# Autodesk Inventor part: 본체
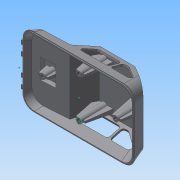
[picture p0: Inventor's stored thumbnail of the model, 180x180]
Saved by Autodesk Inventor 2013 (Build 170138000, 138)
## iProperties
Created: 2015-05
Part Number: 본체
Material: 일반
Document SubType Name: Modeling
Designer: ST3
Density: 1 g/cm^3
Author: ST3
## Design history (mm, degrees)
sketch "스케치1"
  geometry: L1 (-61, 0)-(61, 0); L2 (-61, 0)-(-58.588, 9); L3 (-58.588, 9)-(-19, 11.075); L4 (-19, 11.075)-(-6.549, 31); L5 (-6.549, 31)-(31, 31); L6 (31, 31)-(61, 11); L7 (57.412, 13.392)-(61, 0); L8 (61, 0)-(61, 11); 2 further points
  constraints: 16 end point, 2 horizontal, 2 midpoint, 1 coincident, 1 perpendicular, 1 point on line
  dimensions: "d0" = 122 distance of L1.start L1.end; "d2" = 105 deg angle of L1 L2; "d4" = 42 horizontal distance of L3.end L1.start; "d5" = 30 horizontal distance of L5.end L1.end; "d7" = 31 vertical distance of L1.end L5.end; "d8" = 125 deg angle of L4 L3; "d9" = 9 vertical distance of L2.end L1.start; "d10" = 3 deg angle of L1 L3; "d11" = 105 deg angle of L1 L7; "d99" = 20 vertical distance of L6.end L5.end
extrude "돌출1" new body sketch "스케치1" stored distance "d12" = 76; taper "d13" = 0 deg
sketch "스케치2"
  geometry: L1 (31, 38)-(11.075, 38) reference; L2 (31, -38)-(31, 38) reference; L3 (0, 38)-(31, 29.694); L4 (0, -38)-(31, -29.694); L5 (11.075, -38)-(31, -38) reference; L6 (0, -38)-(9, -38) reference; L7 (9, -38)-(11.075, -38) reference; L8 (11.075, 38)-(9, 38) reference; L9 (0, 38)-(31, 38); L10 (31, 38)-(31, 29.694); L11 (31, -29.694)-(31, -38); L12 (31, -38)-(0, -38); 1 further point
  constraints: 12 end point, 3 collinear, 2 point on line, 1 perpendicular
extrude "돌출2" cut sketch "스케치2" stored distance "d16" = 130; taper "d17" = 0 deg
sketch "스케치3"
  geometry: L1 (-58.588, 9)-(-61, 0) reference; L2 (-19, 11.075)-(-58.588, 9) reference; L3 (-50.479, 9.425)-(-50.741, 14.418); L4 (-50.741, 14.418)-(-30.741, 15.466); L5 (-30.741, 15.466)-(-30.479, 10.473); 1 further point
  constraints: 6 end point, 3 perpendicular, 2 point on line
  dimensions: "d18" = 20 horizontal distance of L3.end L4.end; "d20" = 11 distance from line of L3 L1.end; "d21" = 5 distance between parallel lines of L2 L4
extrude "돌출3" join sketch "스케치3" stored distance "d22" = 26; taper "d23" = 0 deg
feature "쉘1" dims "d24" = 2
sketch "스케치4"
  geometry: L1 (122, -76)-(122, 0) reference; L2 (0, 0)-(122, 0) reference; L3 (0, 0)-(0, -76) reference; L4 (122, -76)-(0, -76) reference; L5 (121, -1)-(121, -75); L6 (121, -75)-(1, -75); L7 (1, -75)-(1, -1); L8 (1, -1)-(121, -1); 1 further point
  constraints: 8 end point, 3 other
  dimensions: "d25" = 1 distance between parallel lines of L2 L8
extrude "돌출4" cut sketch "스케치4" distance "d26" = 1; taper "d27" = 0 deg
sketch "스케치6"
  geometry: L1 (121.732, -0.268)-(121.732, -75.732) reference; C1 r 3 at (100.732, -38); 1 further point
  constraints: 1 centre point, 1 horizontal alignment
  dimensions: "d33" = 6 diameter of C1; "d35" = 21 distance from line of L1 C1.centre
extrude "돌출5" join sketch "스케치6" stored distance "d36" = 10; taper "d37" = 2 deg
sketch "스케치8"
  geometry: L1 (34.732, 2)-(44.732, 2); L2 (58.929, 0)-(-58.929, 0) reference; L3 (34.732, 2)-(29.619, 31); L4 (44.732, 2)-(47.863, 19.758); L5 (42.732, 1)-(36.732, 1) reference; L6 (39.732, 1)-(39.732, 25.179); L7 (57.412, 13.392)-(31, 31) reference; L8 (31, 31)-(-6.549, 31) reference; 1 further point
  constraints: 8 end point, 3 point on line, 1 horizontal, 1 midpoint, 1 perpendicular
  dimensions: "d38" = 2 distance between parallel lines of L2 L1; "d39" = 20 deg angle of L4 L3; "d40" = 10 deg angle of L6 L3; "d41" = 5 distance from line of L6 L1.start; "d42" = 10 distance of L1.end L1.start
extrude "돌출6" join sketch "스케치8" stored distance "d43" = 2; taper "d44" = 0 deg
feature "면 기울기1" dims angle "d45" = 2.5 deg
feature "면 기울기2" dims angle "d46" = 2.5 deg
feature "면 기울기3" dims angle "d47" = 2.5 deg
feature "면 기울기4" dims angle "d48" = 2.5 deg
feature "면 기울기5" dims angle "d49" = 2.5 deg
feature "면 기울기6" dims angle "d50" = 2.5 deg
feature "면 기울기7" dims angle "d51" = 2.5 deg
feature "면 기울기8" dims angle "d52" = 2.5 deg
sketch "스케치9"
  geometry: L1 (-50.741, 14.418)-(-30.741, 15.466) reference; L2 (-50.741, 14.418)-(-30.741, 15.466); L3 (-30.945, 15.456)-(-26.502, 34.9); L4 (-26.502, 34.9)-(-51.656, 31.886); L5 (-51.656, 31.886)-(-50.741, 14.418); 1 further point
  constraints: 8 end point, 1 collinear, 1 perpendicular, 1 point on line
extrude "돌출7" cut sketch "스케치9" stored distance "d53" = 20; taper "d54" = 0 deg
sketch "스케치10"
  geometry: L1 (121.732, -0.268)-(121.732, -75.732) reference; C1 r 3 at (60.732, -60); 1 further point
  constraints: 1 centre point
  dimensions: "d55" = 61 distance from line of L1 C1.centre; "d56" = 22 vertical distance of C1.centre point (61, -38); "d57" = 6 diameter of C1
extrude "돌출8" join sketch "스케치10" stored distance "d58" = 20; taper "d59" = 2 deg
node "작업 평면1"
sketch "스케치11"
  geometry: L1 (3.268, 1)-(-2.732, 1) reference; L2 (4.246, 29)-(-3.71, 29) reference; L3 (3.268, 1)-(4.246, 29) reference; L4 (-30.394, 29)-(-55.675, 12.146) reference; L5 (-55.675, 12.146)-(-58.929, 0) reference; L6 (58.929, 0)-(-58.929, 0) reference; L7 (58.929, 0)-(57.033, 7.079) reference; L8 (57.033, 7.079)-(17.856, 9.132) reference; L9 (17.856, 9.132)-(5.441, 29) reference; L10 (5.441, 29)-(-30.394, 29) reference; L11 (-2.732, 1)-(-3.71, 29) reference; L12 (-4.732, 3)-(5.268, 3); L13 (5.268, 3)-(8.882, 23.494); L14 (-4.732, 3)-(-9.317, 29); L15 (0.268, 1)-(0.268, 29); 1 further point
  constraints: 8 end point, 2 midpoint, 2 point on line, 1 parallel, 1 perpendicular
  dimensions: "d61" = 20 deg angle of L13 L14; "d62" = 10 deg angle of L15 L14; "d63" = 2 distance between parallel lines of L12 L1; "d64" = 10 distance of L12.end L12.start; "d65" = 5 distance from line of L15 L12.start
extrude "돌출9" join sketch "스케치11" stored distance "d66" = 2; taper "d67" = 0 deg
feature "면 기울기9" dims angle "d68" = 2.5 deg
feature "면 기울기10" dims angle "d69" = 2.5 deg
feature "면 기울기11" dims angle "d70" = 2.5 deg
feature "면 기울기12" dims angle "d71" = 2.5 deg
sketch "스케치12"
  geometry: C1 r 3 at (0, 0) reference; 2 further points
  constraints: 1 coincident
sketch "스케치13"
  geometry: C1 r 3 at (0, 0) reference; 2 further points
  constraints: 1 coincident
hole "구멍1" sketch "스케치12" diameter "d72" = 3.242; stored, may be unused: countersink angle "d76" = 90 deg, drill point angle "d78" = 118 deg; dims "d73" = 9, "d74" = 4, "d75" = 2, "d77" = 11
sketch "스케치14"
  geometry: C1 r 3 at (0, 0) reference; 2 further points
  constraints: 1 coincident
hole "구멍2" sketch "스케치14" at (0, 0) diameter "d79" = 3.242; stored, may be unused: countersink angle "d83" = 90 deg, drill point angle "d85" = 118 deg; dims "d80" = 9, "d81" = 4, "d82" = 2, "d84" = 11
sketch "스케치16"
  geometry: L1 (67.281, -67.426)-(67.281, 8.038) reference; 2 further points
  constraints: 1 horizontal alignment, 1 other
  dimensions: "d90" = 50 distance from line of L1 point (17.281, -29.694)
feature "엠보싱1" sketch "스케치16" dims "d91" = 0.5, "d92" = 0
fillet "모깎기1" dims "d93" = 12
fillet "모깎기2" dims "d94" = 12
fillet "모깎기3" dims "d95" = 12
fillet "모깎기4" dims "d96" = 12
sketch "스케치18"
  geometry: L1 (37.549, 0)-(49.849, -8.489) reference; L2 (0, 0)-(37.549, 0) reference; L3 (-12.451, -20.628)-(0, 0) reference; L4 (57.725, -20)-(35.991, -5); L5 (35.991, -5)-(2.822, -5); L6 (2.822, -5)-(-6.231, -20); L7 (-42.592, -31.058)-(55.69, -31.058) reference; L8 (-6.231, -20)-(57.725, -20); L9 (27.769, -5)-(27.769, -20); L10 (29.725, -5)-(29.725, -20); 5 further points; 2 other entities
  constraints: 12 end point, 4 point on line, 2 parallel, 2 perpendicular, 2 other
  dimensions: "d100" = 5 distance between parallel lines of L2 L5; "d101" = 15 vertical distance of L6.end L5.end; "d102" = 15 vertical distance of L4.start L4.end; "d103" = 5 distance between parallel lines of L6 L3; "d104" = 5 distance between parallel lines of L1 L4; "d105" = 34 distance from line of L9 L6.end; "d106" = 28 distance from line of L4.start L10
extrude "돌출10" cut sketch "스케치18" stored distance "d107" = 2; taper "d108" = 0 deg
fillet "모깎기5" dims "d109" = 3
node "작업 평면3"
sketch "스케치19"
  geometry: 1 further point
node "작업 평면4"
sketch "스케치20"
  geometry: L1 (-26.141, 0)-(26.141, 0) reference; A1 r 2 centre (-21, 0) between (-19, 0) and (-23, 0); A2 r 2 centre (-10, 0) between (-8, 0) and (-12, 0); 1 further point
  constraints: 6 point on line, 4 point on circle, 2 centre point
  dimensions: "d112" = 4 diameter of A2; "d114" = 4 diameter of A1; "d115" = 11 distance of A2.centre A1.centre; "d116" = 10 horizontal distance of point (0, -4.177) A2.centre
extrude "돌출11" join sketch "스케치20" stored distance "d117" = 2; taper "d118" = 0 deg
node "솔리드1"
mirror "대칭1"
mirror "대칭2"
mirror "대칭3"
mirror "대칭4"
mirror "대칭5"
mirror "대칭6"
mirror "대칭7"
mirror "대칭8"
node "투영된 루프2"
node "투영된 루프3"
node "작업 평면2"
other parameters: "d60" = -22, "d110" = 90 deg, "d111" = 2
